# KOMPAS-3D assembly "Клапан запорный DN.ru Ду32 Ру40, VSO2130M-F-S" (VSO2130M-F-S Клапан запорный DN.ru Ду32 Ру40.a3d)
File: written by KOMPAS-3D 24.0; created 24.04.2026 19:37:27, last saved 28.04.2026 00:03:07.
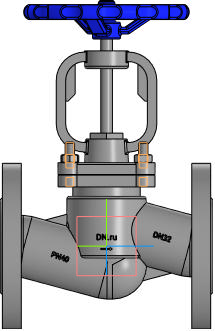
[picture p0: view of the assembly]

Document properties: Автор: DN.ru; Полное имя файла: C:\Работа\ГОТОВЫЕ ИСХОДНИКИ\VSO2130M-F-S Клапан запорный сальниковый DN.ru Ду15-100 Ру40\исходные материалы\DN32\VSO2130M-F-S Клапан запорный DN.ru Ду32 Ру40.a3d

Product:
- Component [detail]: Корпус  | qty 1  | pos. 1  | Масса: 6.9; Автор: R2D2; source file: Korpus.m3d
- Component [detail]: Деталь  | qty 1  | pos. 2  | Масса: 1.052379; Автор: mrdid; source file: rama.m3d
- Component [detail]: Деталь2  | qty 1  | pos. 3  | Масса: 0.594157; Автор: R2D2; additional columns: Типовые; source file: shturval.m3d
- Component [standard]: Шпилька М8-6gx30 ГОСТ 22032-76  | qty 4  | Масса: 0.01271; Раздел спецификации: Стандартные изделия; Рассекать на разрезах: no
- Component [standard]: Гайка М8-6H ГОСТ 5915-70  | qty 4  | Масса: 0.005548; Раздел спецификации: Стандартные изделия; Рассекать на разрезах: no
- Part/product: Клапан запорный DN.ru Ду32 Ру40  | designation VSO2130M-F-S
    Масса: 7.5
    Раздел спецификации: Прочие изделия
    Примечание: D090-01982

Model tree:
1. Контекстная связь:1  (with: Контекстная связь (Деталь):1)  (labels: Грань.Твердое тело1)
2. Контекстная связь:2  (with: Смещенная плоскость:4, Контекстная связь (Деталь):2)  (labels: Грань.Твердое тело1)
3. Контекстная связь:3  (with: Контекстная связь (Корпус):3)
4. Контекстная связь:4  (with: Эскиз:2, Ребро.Элемент выдавливания:14, Контекстная связь (Деталь):4)
5. Контекстная связь:5  (with: Контекстная связь (Деталь):5)
6. Массив по концентрической сетке:1  (with: Грань.Элемент выдавливания:1, Грань.Элемент выдавливания:15, Грань.Элемент выдавливания:3, Грань.Элемент выдавливания:2, Грань.Элемент выдавливания:16, Грань.Элемент выдавливания:14)  (labels: Грань.Твердое тело1)  (4 pattern instances)
     Шаг 2 = 360; Угол = 9

Referenced files in C:\Работа\ГОТОВЫЕ ИСХОДНИКИ\VSO2130M-F-S Клапан запорный сальниковый DN.ru Ду15-100 Ру40\исходные материалы\DN32\: Korpus.m3d, rama.m3d, shturval.m3d
Referenced files in C:\Program Files\ASCON\KOMPAS-3D v24\Libs\PolynomLib\DATA\vault\Methods\Kompas\3D\: PLib_Stud_1_900.m3d, PLib_Nut_OST92_900.m3d
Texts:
  BOSimple***PART:059b53d5-85de-be37-d9a2-ab7837626634***SHORTLOC:Root±30±20±10±120±10±20[Нет;Без покрытия;Без указания материала;-;8;30;1,25;1,25]
  BOSimple***PART:bd0d297a-feeb-be2b-2a2a-05cd1c87d412***SHORTLOC:Root±30±10±20±©{}110±10±50±60[Нет;Без покрытия;Без указания материала;-;8;1,25;13]
  Программные изделия  и базы данных
  Крепежное изделие ГОСТ
  VSO2130M-F-S
  Деталь2 Деталь2
  Шпилька М8-6gx30 ГОСТ 22032-76 (1)
  cut1
  Гайка М8-6H ГОСТ 5915-70 (1)
  bcut1
  hole1
  hcut1
  hole2
  Шпилька М8-6gx30 ГОСТ 22032-76 (2)
  Гайка М8-6H ГОСТ 5915-70 (2)
  Шпилька М8-6gx30 ГОСТ 22032-76 (3)
  Гайка М8-6H ГОСТ 5915-70 (3)
  Шпилька М8-6gx30 ГОСТ 22032-76 (4)
  Гайка М8-6H ГОСТ 5915-70 (4)
  Плоскость ZX.Начало координат
  Плоскость XY.Начало координат
  Plane. Начало координат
